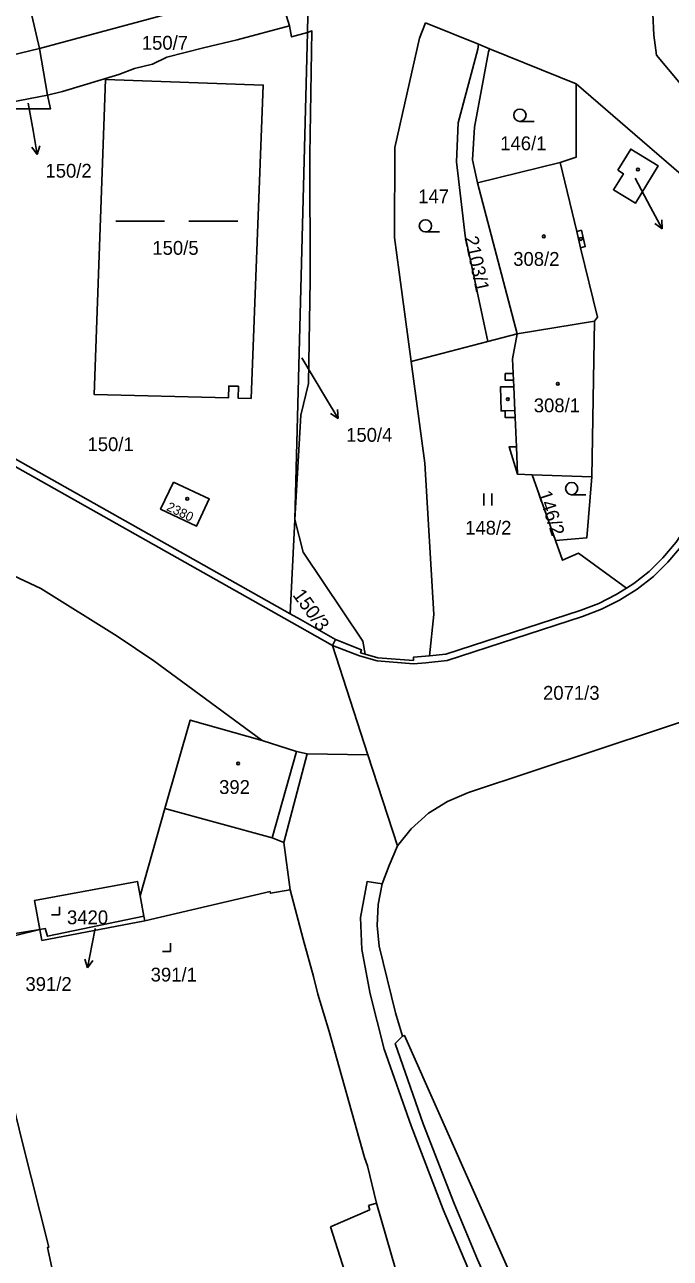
# Model space of a CAD drawing. Extents: x -679220 to -673243, y -1075091 to -1066557.
# Drawn here: x -676808.5 to -676729.1, y -1071521.5 to -1071369.7 of the extents above; entities that cross this region are included whole.
import ezdxf

# ---------------------------------------------------------------- set-up
doc = ezdxf.new("R2010")
doc.units = 0
for name, color, linetype in [('Hranice parcel', 7, 'Continuous'), ('Parcelní čísla', 7, 'Continuous'), ('Pop  PČ popisy', 7, 'Continuous'), ('Vnitřní kresba', 7, 'Continuous'), ('Značky budov', 7, 'Continuous'), ('Značky kultur', 7, 'Continuous')]:
    doc.layers.add(name, color=color, linetype=linetype)

msp = doc.modelspace()

# ---------------------------------------------------------------- linework, layer by layer
at = {"layer": 'Hranice parcel'}
for p, q in [((-676775.94, -1071369.83), (-676777.78, -1071363.89)), ((-676773.58, -1071363.79), (-676773.75, -1071370.63)), ((-676806.71, -1071372.6), (-676808.43, -1071365.09)), ((-676775.28, -1071430.57), (-676773.75, -1071370.63)), ((-676759.2, -1071369.45), (-676752.71, -1071372.09)), ((-676752.71, -1071372.09), (-676751.36, -1071372.63)), ((-676805.7, -1071378.36), (-676806.71, -1071372.6)), ((-676751.36, -1071372.63), (-676740.68, -1071376.97)), ((-676805.7, -1071378.36), (-676810.16, -1071379.22)), ((-676742.67, -1071386.62), (-676752.84, -1071389.15)), ((-676752.84, -1071389.15), (-676747.96, -1071407.71)), ((-676738.45, -1071406.17), (-676747.96, -1071407.71)), ((-676738.77, -1071425.31), (-676738.45, -1071406.17)), ((-676751.55, -1071408.65), (-676760.97, -1071411.13)), ((-676747.96, -1071407.71), (-676751.55, -1071408.65)), ((-676813.11, -1071421.19), (-676775.88, -1071442.17)), ((-676743.23, -1071433.16), (-676746.09, -1071425.05)), ((-676746.09, -1071425.05), (-676738.77, -1071425.31)), ((-676775.88, -1071442.17), (-676775.28, -1071430.57)), ((-676773.77, -1071459.42), (-676766.29, -1071459.51)), ((-676762.66, -1071470.73), (-676766.29, -1071459.51)), ((-676794.31, -1071476.87), (-676793.84, -1071479.38)), ((-676793.84, -1071479.38), (-676793.73, -1071479.96)), ((-676818.29, -1071482.89), (-676806.65, -1071481))]:
    msp.add_line(p, q, dxfattribs=at)
for points in [[(-676711.15, -1071388.7), (-676720.68, -1071385.54), (-676730.79, -1071373.44), (-676731.13, -1071370.95), (-676731.25, -1071368.33), (-676731.11, -1071366.47), (-676729.91, -1071360.31), (-676727.92, -1071354.93), (-676716.83, -1071341.33)], [(-676806.71, -1071372.6), (-676783.69, -1071366.35), (-676780.19, -1071365.08), (-676777.78, -1071363.89)], [(-676775.94, -1071369.83), (-676782.36, -1071371.55), (-676786.52, -1071372.52), (-676791.02, -1071373.68), (-676792.78, -1071374.55), (-676795, -1071375.07), (-676796.92, -1071375.79), (-676803.85, -1071377.9), (-676805.7, -1071378.36)], [(-676773.75, -1071370.63), (-676775.69, -1071371.18), (-676775.94, -1071369.83)], [(-676773.75, -1071370.63), (-676773.19, -1071370.45), (-676773.46, -1071385.69), (-676773.42, -1071401.08), (-676773.62, -1071413.81), (-676774.53, -1071417.74), (-676775.28, -1071430.57)], [(-676760.97, -1071411.13), (-676762.45, -1071400.11), (-676763.03, -1071395.88), (-676762.98, -1071384.79), (-676759.94, -1071371.35), (-676759.2, -1071369.45)], [(-676751.55, -1071408.65), (-676753.51, -1071399.43), (-676754.35, -1071395.67), (-676755.39, -1071386.57), (-676755.2, -1071381.75), (-676752.77, -1071372.69), (-676752.71, -1071372.09)], [(-676921.77, -1071372.81), (-676907.7, -1071373.32), (-676897.48, -1071373.81), (-676881.76, -1071374.51), (-676865.44, -1071375.36), (-676853.12, -1071376.35), (-676839.6, -1071376.93), (-676829.31, -1071377.63), (-676824, -1071376.8), (-676807.89, -1071372.89), (-676806.71, -1071372.6)], [(-676751.36, -1071372.63), (-676751.46, -1071373.03), (-676753.2, -1071382.27), (-676753.43, -1071386.29), (-676752.84, -1071389.15)], [(-676780.64, -1071415.67), (-676782.26, -1071415.63), (-676782.22, -1071414.17), (-676783.42, -1071414.14), (-676783.46, -1071415.6), (-676799.97, -1071415.18), (-676798.58, -1071376.42), (-676779.17, -1071377.11), (-676780.64, -1071415.67)], [(-676740.68, -1071376.97), (-676740.7, -1071385.98), (-676742.67, -1071386.62)], [(-676740.68, -1071376.97), (-676721.46, -1071393.56), (-676721.5, -1071397.04), (-676721.26, -1071402.92), (-676721.75, -1071405.37), (-676721.92, -1071406.25), (-676723.65, -1071414.33), (-676718.73, -1071416.13)], [(-676805.7, -1071378.36), (-676805.35, -1071380.03), (-676810.17, -1071380.03)], [(-676735.58, -1071387.59), (-676733.97, -1071384.99), (-676730.59, -1071387.06), (-676733.4, -1071391.65), (-676736.1, -1071389.98), (-676734.88, -1071388.02), (-676735.58, -1071387.59)], [(-676738.45, -1071406.17), (-676738.08, -1071405.67), (-676740.14, -1071397.13), (-676739.56, -1071396.99), (-676740.05, -1071394.97), (-676740.62, -1071395.11), (-676742.67, -1071386.62)], [(-676747.96, -1071407.71), (-676748.52, -1071410.78), (-676748.44, -1071412.59), (-676749.4, -1071412.61), (-676749.4, -1071413.42), (-676748.4, -1071413.41), (-676748.36, -1071414.22), (-676749.98, -1071414.22), (-676749.93, -1071417.2), (-676749.43, -1071417.19), (-676749.41, -1071418.03), (-676748.19, -1071418), (-676748.03, -1071421.63), (-676748.93, -1071421.64), (-676747.89, -1071424.99), (-676746.09, -1071425.05)], [(-676760.97, -1071411.13), (-676759.29, -1071423.62), (-676758.21, -1071442.25), (-676758.73, -1071447.33)], [(-676738.77, -1071425.31), (-676739.38, -1071432.84), (-676743.23, -1071433.16)], [(-676790.23, -1071425.98), (-676785.81, -1071428.04), (-676787.38, -1071431.37), (-676791.8, -1071429.28), (-676790.23, -1071425.98)], [(-676766.63, -1071447.13), (-676766.92, -1071445.54), (-676774.26, -1071434.59), (-676775.28, -1071430.57)], [(-676734.5, -1071439.01), (-676733.6, -1071438.44), (-676731.7, -1071436.98), (-676730.01, -1071435.3), (-676728.37, -1071433.36), (-676726.99, -1071431.27)], [(-676734.5, -1071439.01), (-676740.39, -1071434.72), (-676742.38, -1071435.57), (-676743.23, -1071433.16)], [(-676779.29, -1071457.75), (-676792.63, -1071447.96), (-676797.15, -1071444.93), (-676806.53, -1071439.04), (-676813.29, -1071435.89)], [(-676758.73, -1071447.33), (-676756.71, -1071447.14), (-676740.2, -1071441.76), (-676737.88, -1071440.89), (-676735.77, -1071439.8), (-676734.5, -1071439.01)], [(-676775.88, -1071442.17), (-676774.6, -1071442.89), (-676770.3, -1071445.35)], [(-676766.29, -1071459.51), (-676770.64, -1071446.07), (-676770.3, -1071445.35)], [(-676770.3, -1071445.35), (-676767.1, -1071446.59), (-676767.21, -1071446.97), (-676766.63, -1071447.13)], [(-676766.63, -1071447.13), (-676765.06, -1071447.57), (-676760.7, -1071447.91), (-676760.7, -1071447.51), (-676758.73, -1071447.33)], [(-676706.46, -1071448.39), (-676753.93, -1071464.16), (-676756.51, -1071465.26), (-676758.86, -1071466.72), (-676760.97, -1071468.64), (-676762.66, -1071470.73)], [(-676779.29, -1071457.75), (-676788.15, -1071455.25), (-676791.29, -1071466.12), (-676794.31, -1071476.87)], [(-676773.77, -1071459.42), (-676775.08, -1071459.11), (-676779.29, -1071457.75)], [(-676775.85, -1071476.13), (-676776.64, -1071470.3), (-676773.77, -1071459.42)], [(-676764.54, -1071475.38), (-676763.69, -1071473.15), (-676762.66, -1071470.73)], [(-676806.65, -1071481), (-676807.31, -1071477.46), (-676794.65, -1071475.1), (-676794.31, -1071476.87)], [(-676753.54, -1071523.73), (-676757.03, -1071515.47), (-676760.96, -1071505.19), (-676764.28, -1071495.76), (-676766.04, -1071488.95), (-676767.03, -1071483.49), (-676767.2, -1071479.54), (-676766.39, -1071475.11), (-676764.54, -1071475.38)], [(-676764.54, -1071475.38), (-676765.03, -1071477.96), (-676765.17, -1071480.52), (-676764.91, -1071483.06), (-676762.89, -1071491.26), (-676762.03, -1071494.13)], [(-676793.73, -1071479.96), (-676778.34, -1071476.35), (-676778.3, -1071476.55), (-676775.85, -1071476.13)], [(-676775.85, -1071476.13), (-676774.25, -1071482.22), (-676773, -1071486.82), (-676772.46, -1071488.98), (-676771.07, -1071493.58), (-676766.7, -1071509.07), (-676766.37, -1071510.09), (-676765.26, -1071514.71), (-676761.72, -1071526.9), (-676760.25, -1071531.41), (-676759.56, -1071533.91), (-676756.1, -1071546.01)], [(-676793.84, -1071479.38), (-676805.72, -1071481.85), (-676805.99, -1071480.9), (-676806.65, -1071481)], [(-676793.73, -1071479.96), (-676806.39, -1071482.37), (-676806.65, -1071481)], [(-676806.65, -1071481), (-676815.01, -1071483.07), (-676812.2, -1071493.43)], [(-676804.95, -1071523.55), (-676805.72, -1071520.17), (-676805.55, -1071520.12), (-676808.81, -1071507.1), (-676812.2, -1071493.43)], [(-676762.03, -1071494.13), (-676762.94, -1071495.05), (-676759.5, -1071504.94), (-676755.7, -1071514.74), (-676752.84, -1071521.62), (-676750.39, -1071527.09), (-676748.58, -1071527.96), (-676747.78, -1071528.25), (-676742.3, -1071540.02), (-676742.65, -1071540.18), (-676742.64, -1071543.96), (-676732.93, -1071565.35), (-676728.85, -1071575.59), (-676726.29, -1071582.59), (-676724.59, -1071589.37), (-676723.72, -1071596.33), (-676723.48, -1071603.98), (-676723.51, -1071620.81), (-676724.06, -1071638.73), (-676724.85, -1071648.2), (-676725.15, -1071652.2), (-676724.86, -1071656.66), (-676723.85, -1071663.89)], [(-676762.03, -1071494.13), (-676761.82, -1071494.06), (-676721.65, -1071584.53), (-676720.32, -1071587.99), (-676719.96, -1071590.96), (-676720.27, -1071640.98), (-676720.61, -1071652.09)]]:
    msp.add_lwpolyline(points, dxfattribs=at)
at = {"layer": 'Pop  PČ popisy'}
for p, q in [((-676808.08, -1071379.35), (-676807.49, -1071382.7)), ((-676807.49, -1071382.7), (-676806.97, -1071385.66)), ((-676806.97, -1071385.66), (-676807.64, -1071384.76)), ((-676806.97, -1071385.66), (-676806.65, -1071384.58)), ((-676733.43, -1071388.56), (-676731.53, -1071392.14)), ((-676731.53, -1071392.14), (-676730.12, -1071394.79)), ((-676730.12, -1071394.79), (-676731.03, -1071394.14)), ((-676730.12, -1071394.79), (-676730.15, -1071393.67)), ((-676774.41, -1071410.67), (-676771.51, -1071415.57)), ((-676771.51, -1071415.57), (-676769.96, -1071418.14)), ((-676769.96, -1071418.14), (-676770.91, -1071417.54)), ((-676769.96, -1071418.14), (-676770.05, -1071417.03)), ((-676799.85, -1071480.88), (-676800.23, -1071482.79)), ((-676800.23, -1071482.79), (-676800.8, -1071485.74)), ((-676800.8, -1071485.74), (-676801.1, -1071484.66)), ((-676800.8, -1071485.74), (-676800.12, -1071484.85))]:
    msp.add_line(p, q, dxfattribs=at)
at = {"layer": 'Vnitřní kresba'}
for p, q in [((-676740.62, -1071395.11), (-676740.14, -1071397.13)), ((-676748.44, -1071412.59), (-676748.4, -1071413.41)), ((-676748.36, -1071414.22), (-676748.23, -1071417.17)), ((-676749.43, -1071417.19), (-676748.23, -1071417.17)), ((-676748.23, -1071417.17), (-676748.19, -1071418)), ((-676774.99, -1071443.59), (-676818.03, -1071419.33)), ((-676748.03, -1071421.63), (-676747.89, -1071424.99)), ((-676729.4, -1071435.82), (-676727.73, -1071433.84)), ((-676731.17, -1071437.58), (-676729.4, -1071435.82)), ((-676733.2, -1071439.14), (-676731.17, -1071437.58)), ((-676737.55, -1071441.62), (-676735.34, -1071440.48)), ((-676735.34, -1071440.48), (-676733.2, -1071439.14)), ((-676739.92, -1071442.51), (-676737.55, -1071441.62)), ((-676756.56, -1071447.93), (-676739.92, -1071442.51)), ((-676770.64, -1071446.07), (-676774.99, -1071443.59)), ((-676767.32, -1071447.36), (-676770.64, -1071446.07)), ((-676767.32, -1071447.36), (-676765.15, -1071447.97)), ((-676765.15, -1071447.97), (-676760.69, -1071448.31)), ((-676759.18, -1071448.22), (-676756.56, -1071447.93)), ((-676760.69, -1071448.31), (-676759.18, -1071448.22)), ((-676775.08, -1071459.11), (-676778.09, -1071469.74)), ((-676778.09, -1071469.74), (-676791.29, -1071466.12)), ((-676778.09, -1071469.74), (-676776.64, -1071470.3)), ((-676766.22, -1071514.99), (-676765.26, -1071514.71)), ((-676770.91, -1071517.6), (-676766.07, -1071515.51)), ((-676766.07, -1071515.51), (-676766.22, -1071514.99)), ((-676766.03, -1071532.96), (-676770.91, -1071517.6))]:
    msp.add_line(p, q, dxfattribs=at)
at = {"layer": 'Značky budov'}
for centre in [(-676733.09, -1071387.5), (-676744.67, -1071395.73), (-676740.1, -1071396.04), (-676742.95, -1071413.87), (-676749.09, -1071415.75), (-676788.52, -1071428.02), (-676782.26, -1071460.6)]:
    msp.add_circle(centre, 0.175, dxfattribs=at)
at = {"layer": 'Značky kultur'}
for p, q in [((-676747.6, -1071381.57), (-676745.85, -1071381.57)), ((-676797.31, -1071393.86), (-676791.31, -1071393.86)), ((-676788.31, -1071393.86), (-676782.31, -1071393.86)), ((-676759.23, -1071395.18), (-676757.48, -1071395.18)), ((-676752.05, -1071428.85), (-676752.05, -1071427.35)), ((-676751.05, -1071428.85), (-676751.05, -1071427.35)), ((-676741.24, -1071427.51), (-676739.49, -1071427.51)), ((-676804.22, -1071479.22), (-676804.22, -1071478.22)), ((-676805.22, -1071479.22), (-676804.22, -1071479.22)), ((-676790.58, -1071483.71), (-676790.58, -1071482.71)), ((-676791.58, -1071483.71), (-676790.58, -1071483.71))]:
    msp.add_line(p, q, dxfattribs=at)
for centre in [(-676747.6, -1071380.82), (-676759.23, -1071394.43), (-676741.24, -1071426.76)]:
    msp.add_circle(centre, 0.75, dxfattribs=at)

# ---------------------------------------------------------------- texts
at = {"layer": 'Parcelní čísla'}
for s, p in [('150/7', (-676794.11, -1071372.75)), ('146/1', (-676750.03, -1071385.12)), ('150/2', (-676805.96, -1071388.5)), ('147', (-676760.12, -1071391.65)), ('150/5', (-676792.81, -1071397.99)), ('308/2', (-676748.43, -1071399.35)), ('308/1', (-676745.9, -1071417.37)), ('150/4', (-676768.98, -1071421)), ('150/1', (-676800.79, -1071422.15)), ('148/2', (-676754.34, -1071432.43)), ('2071/3', (-676744.76, -1071452.75)), ('392', (-676784.6, -1071464.34)), ('3420', (-676803.31, -1071480.37)), ('391/1', (-676793.02, -1071487.42)), ('391/2', (-676808.42, -1071488.58))]:
    msp.add_text(s, height=1.7, dxfattribs=at).set_placement(p)
for s, height, rotation, p in [('2103/1', 1.7, 282, (-676754.43, -1071395.87)), ('146/2', 1.7, 288, (-676745.42, -1071427.32)), ('2380', 1.14, 334, (-676791.16, -1071429.38)), ('150/3', 1.7, 306, (-676775.63, -1071439.87))]:
    msp.add_text(s, height=height, rotation=rotation, dxfattribs=at).set_placement(p)

doc.saveas('drawing.dxf')
